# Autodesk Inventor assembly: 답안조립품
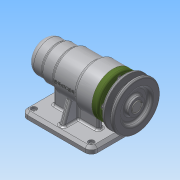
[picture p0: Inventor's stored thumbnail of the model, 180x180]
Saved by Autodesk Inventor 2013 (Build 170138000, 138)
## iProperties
Created: 2016-06
Part Number: 답안조립품
Document SubType Name: Assembly
Designer: Administrator
Author: Administrator
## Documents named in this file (11)
- C:\Users\Administrator\Desktop\460608V1017\답안조립품.iam
- C:\Users\Administrator\Desktop\460608V1017\본체.ipt
- C:\Users\Administrator\Desktop\460608V1017\베어링 51202.ipt
- C:\Users\Administrator\Desktop\460608V1017\어댑터슬리브.ipt
- C:\Users\Administrator\Desktop\460608V1017\축.ipt
- C:\Users\Administrator\Desktop\460608V1017\베어링 6004.ipt
- C:\Users\Administrator\Desktop\460608V1017\볼트 M4 x 12.ipt
- C:\Users\Administrator\Desktop\460608V1017\커버.ipt
- C:\Users\Administrator\Desktop\460608V1017\키 5 x 5 x 16.ipt
- C:\Users\Administrator\Desktop\460608V1017\V벨트풀리.ipt
- C:\Users\Administrator\Desktop\460608V1017\멈춤나사 M3x8.ipt
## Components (6 placed, 2 different names)
1. ISO 4762 M4 x 12:1
2. V벨트풀리:1 — 각도:1
3. ISO 4762 M4 x 12:2
4. ISO 4762 M4 x 12:3
5. ISO 4762 M4 x 12:4
6. ISO 4762 M4 x 12:5
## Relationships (1: Angle 1)
- 각도:1 [Angle]: V벨트풀리:1
